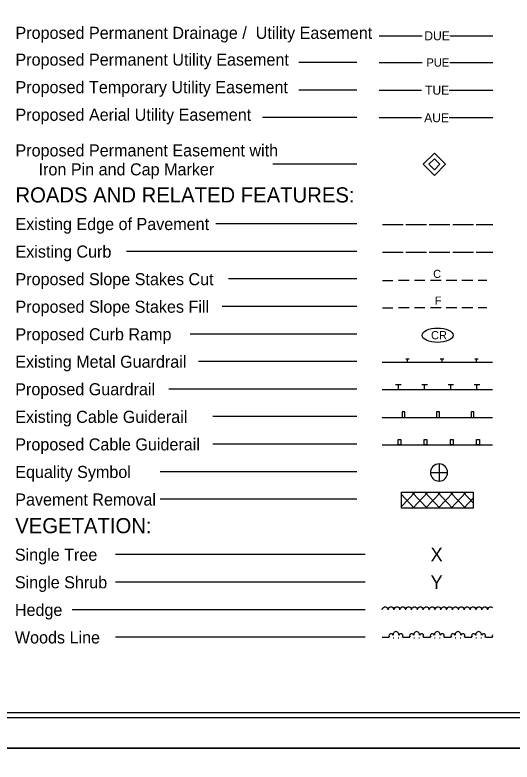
# Model space of a CAD drawing. Extents: x 2241278 to 2254132, y 649924 to 670434.
# Drawn here: x 2247365 to 2249169, y 655349 to 658059 of the extents above; entities that cross this region are included whole.
import ezdxf

# ---------------------------------------------------------------- set-up
doc = ezdxf.new("R2010")
doc.units = 0
for name, color, linetype in [('Prop Easement Permanent Drainage Utility', 7, 'Continuous'), ('Prop ROW Permanent Easement CELL', 7, 'Continuous'), ('Prop WCC CELL', 7, 'Continuous'), ('Sheet Cutting Line CELL', 7, 'Continuous'), ('Sheet Plot Border Inside CELL', 7, 'Continuous'), ('Sheet Plot Border Outside CELL', 7, 'Continuous'), ('Sheet Symbology CELL', 7, 'Continuous')]:
    doc.layers.add(name, color=color, linetype=linetype)

msp = doc.modelspace()

# ---------------------------------------------------------------- linework, layer by layer
at = {"layer": 'Prop Easement Permanent Drainage Utility'}
for p, q in [((2248686.3, 657983.7), (2248842.8, 657983.7)), ((2248942.8, 657983.7), (2249098.8, 657983.7))]:
    msp.add_line(p, q, dxfattribs=at)
at = {"layer": 'Prop ROW Permanent Easement CELL'}
msp.add_line((2248887, 657517.5), (2248887, 657517.5), dxfattribs=at)
for points in [[(2248887, 657557.7), (2248927.2, 657517.5), (2248887, 657477.2), (2248846.7, 657517.5)], [(2248887, 657537.6), (2248907.1, 657517.5), (2248887, 657497.3), (2248866.9, 657517.5)]]:
    msp.add_lwpolyline(points, close=True, dxfattribs=at)
at = {"layer": 'Prop WCC CELL'}
msp.add_ellipse((2248898.6, 656897.4), major_axis=(56.1, 0), ratio=0.462467, dxfattribs=at)
at = {"layer": 'Sheet Cutting Line CELL'}
for p, q in [((2252976.3, 655399.2), (2244558.8, 655399.2)), ((2244558.8, 655399.2), (2252978.8, 655399.2))]:
    msp.add_line(p, q, dxfattribs=at)
at = {"layer": 'Sheet Plot Border Inside CELL'}
msp.add_lwpolyline([(2244623.8, 655511.4), (2252956.3, 655511.4), (2252956.3, 660786.9), (2244623.8, 660786.9)], close=True, dxfattribs=at)
at = {"layer": 'Sheet Plot Border Outside CELL'}
for points in [[(2244558.8, 655399.2), (2252978.8, 655399.2), (2252978.8, 660899.2), (2244558.8, 660899.2)], [(2244558.8, 649924.2), (2252976.3, 649924.2), (2252976.3, 655399.2), (2244558.8, 655399.2)]]:
    msp.add_lwpolyline(points, close=True, dxfattribs=at)
at = {"layer": 'Sheet Symbology CELL'}
for p, q in [((2248606.1, 657886.6), (2248395.4, 657886.6)), ((2248686.3, 657886.6), (2248705.5, 657886.6)), ((2248705.5, 657886.6), (2248843, 657886.6)), ((2248943, 657886.6), (2249080.5, 657886.6)), ((2249080.5, 657886.6), (2249098.8, 657886.6)), ((2248606.1, 657786.6), (2248395.4, 657786.6)), ((2248686.3, 657786.6), (2248703, 657786.6)), ((2248703, 657786.6), (2248840.5, 657786.6)), ((2248940.5, 657786.6), (2249078, 657786.6)), ((2249078, 657786.6), (2249098.8, 657786.6)), ((2248606.1, 657686.6), (2248263.8, 657686.6)), ((2248686.3, 657686.6), (2248703, 657686.6)), ((2248703, 657686.6), (2248840.5, 657686.6)), ((2248940.5, 657686.6), (2249078, 657686.6)), ((2249078, 657686.6), (2249098.8, 657686.6)), ((2248606.1, 657517.5), (2248301.1, 657517.5)), ((2248606.1, 657301.7), (2248094.4, 657301.7)), ((2248698.8, 657298.8), (2248773.8, 657298.8)), ((2248783.8, 657298.8), (2248858.8, 657298.8)), ((2248868.8, 657298.8), (2248943.8, 657298.8)), ((2248953.8, 657298.8), (2249028.8, 657298.8)), ((2249038.8, 657298.8), (2249098.8, 657298.8)), ((2248606.1, 657201.7), (2247770.4, 657201.7)), ((2248698.8, 657198.8), (2248773.8, 657198.8)), ((2248783.8, 657198.8), (2248858.8, 657198.8)), ((2248868.8, 657198.8), (2248943.8, 657198.8)), ((2248953.8, 657198.8), (2249028.8, 657198.8)), ((2249038.8, 657198.8), (2249098.8, 657198.8)), ((2248606.1, 657101.7), (2248140.2, 657101.7)), ((2248698.8, 657096.4), (2248736.8, 657096.4)), ((2248795.3, 657096.4), (2248757.5, 657096.4)), ((2248852.8, 657096.4), (2248814.8, 657096.4)), ((2248911.5, 657096.4), (2248872.5, 657096.4)), ((2248968.8, 657096.4), (2248930, 657096.4)), ((2249026.5, 657096.4), (2248987.3, 657096.4)), ((2249078, 657096.4), (2249046, 657096.4)), ((2248606.1, 657001.7), (2248117.4, 657001.7)), ((2248698.8, 656996.4), (2248736.8, 656996.4)), ((2248795.3, 656996.4), (2248757.5, 656996.4)), ((2248852.8, 656996.4), (2248814.8, 656996.4)), ((2248911.5, 656996.4), (2248872.5, 656996.4)), ((2248968.8, 656996.4), (2248930, 656996.4)), ((2249026.5, 656996.4), (2248987.3, 656996.4)), ((2249078, 656996.4), (2249046, 656996.4)), ((2248606.1, 656901.7), (2248001.5, 656901.7)), ((2248605.3, 656802.3), (2248031.1, 656802.3)), ((2248783.7, 656811.9), (2248796.2, 656811.9)), ((2248789.9, 656799.4), (2248789.9, 656811.9)), ((2248908.7, 656811.9), (2248921.2, 656811.9)), ((2248914.9, 656799.4), (2248914.9, 656811.9)), ((2249033.7, 656811.9), (2249046.2, 656811.9)), ((2249039.9, 656799.4), (2249039.9, 656811.9)), ((2248698, 656799.4), (2249098, 656799.4)), ((2248746.6, 656719.2), (2248766.6, 656719.2)), ((2248756.6, 656699.4), (2248756.6, 656719.2)), ((2248841.6, 656719.2), (2248861.6, 656719.2)), ((2248851.6, 656699.4), (2248851.6, 656719.2)), ((2248936.6, 656719.2), (2248956.6, 656719.2)), ((2248946.6, 656699.4), (2248946.6, 656719.2)), ((2249031.6, 656719.2), (2249051.6, 656719.2)), ((2249041.6, 656699.4), (2249041.6, 656719.2)), ((2248605.3, 656702.3), (2247924.1, 656702.3)), ((2249098, 656699.4), (2248698, 656699.4)), ((2248605.3, 656602.3), (2248083.8, 656602.3)), ((2248698, 656599.4), (2249098, 656599.4)), ((2248605.3, 656502.3), (2248083.8, 656502.3)), ((2248698, 656499.4), (2249098, 656499.4)), ((2248904.1, 656430.6), (2248904.1, 656399.3)), ((2248605.3, 656402.3), (2247892.2, 656402.3)), ((2248872.9, 656399.3), (2248904.1, 656399.3)), ((2248904.1, 656399.3), (2248904.1, 656368.1)), ((2248904.1, 656399.3), (2248935.4, 656399.3)), ((2248767.7, 656328.7), (2249028.2, 656328.7)), ((2248767.7, 656270.2), (2248767.7, 656328.7)), ((2248767.7, 656325.7), (2248770.5, 656328.7)), ((2248767.7, 656276), (2248817, 656328.7)), ((2248814, 656270.2), (2248767.7, 656319.7)), ((2248860.5, 656270.2), (2248805.5, 656328.7)), ((2248808.5, 656270.2), (2248863.5, 656328.7)), ((2248906.7, 656270.2), (2248852, 656328.7)), ((2248854.7, 656270.2), (2248910, 656328.7)), ((2248953.2, 656270.2), (2248898.2, 656328.7)), ((2248901.2, 656270.2), (2248956.2, 656328.7)), ((2248999.7, 656270.2), (2248944.5, 656328.7)), ((2248947.7, 656270.2), (2249002.5, 656328.7)), ((2249028.2, 656289), (2248991, 656328.7)), ((2249028.2, 656328.7), (2249028.2, 656270.2)), ((2248605.3, 656302.3), (2247892.2, 656302.3)), ((2248994, 656270.2), (2249028.2, 656306.7)), ((2249028.2, 656270.2), (2248767.7, 656270.2)), ((2248636, 656101.9), (2247730.4, 656101.9)), ((2248636, 656001.9), (2247730.4, 656001.9)), ((2248698, 655901.9), (2248699.5, 655906.7)), ((2248699.5, 655906.7), (2248702.5, 655909.9)), ((2248702.5, 655909.9), (2248706.5, 655912.2)), ((2248706.5, 655912.2), (2248711.2, 655912.2)), ((2248711.2, 655912.2), (2248715.2, 655909.7)), ((2248715.2, 655909.7), (2248718, 655906.4)), ((2248718, 655906.4), (2248719, 655902.2)), ((2248719.2, 655901.9), (2248720.7, 655906.7)), ((2248720.7, 655906.7), (2248723.7, 655909.9)), ((2248723.7, 655909.9), (2248727.7, 655912.2)), ((2248727.7, 655912.2), (2248732.5, 655912.2)), ((2248732.5, 655912.2), (2248736.5, 655909.7)), ((2248736.5, 655909.7), (2248739.2, 655906.4)), ((2248739.2, 655906.4), (2248740.2, 655902.2)), ((2248740.5, 655901.9), (2248742, 655906.7)), ((2248742, 655906.7), (2248745, 655909.9)), ((2248745, 655909.9), (2248749, 655912.2)), ((2248749, 655912.2), (2248753.7, 655912.2)), ((2248753.7, 655912.2), (2248757.7, 655909.7)), ((2248757.7, 655909.7), (2248760.5, 655906.4)), ((2248760.5, 655906.4), (2248761.5, 655902.2)), ((2248761.7, 655901.9), (2248763.2, 655906.7)), ((2248763.2, 655906.7), (2248766.2, 655909.9)), ((2248766.2, 655909.9), (2248770.2, 655912.2)), ((2248770.2, 655912.2), (2248775, 655912.2)), ((2248775, 655912.2), (2248779, 655909.7)), ((2248779, 655909.7), (2248781.7, 655906.4)), ((2248781.7, 655906.4), (2248782.7, 655902.2)), ((2248783, 655901.9), (2248784.5, 655906.7)), ((2248784.5, 655906.7), (2248787.5, 655909.9)), ((2248787.5, 655909.9), (2248791.5, 655912.2)), ((2248791.5, 655912.2), (2248796.2, 655912.2)), ((2248796.2, 655912.2), (2248800.2, 655909.7)), ((2248800.2, 655909.7), (2248803, 655906.4)), ((2248803, 655906.4), (2248804, 655902.2)), ((2248804.2, 655901.9), (2248805.7, 655906.7)), ((2248805.7, 655906.7), (2248808.7, 655909.9)), ((2248808.7, 655909.9), (2248812.7, 655912.2)), ((2248812.7, 655912.2), (2248817.5, 655912.2)), ((2248817.5, 655912.2), (2248821.5, 655909.7)), ((2248821.5, 655909.7), (2248824.2, 655906.4)), ((2248824.2, 655906.4), (2248825.2, 655902.2)), ((2248825.5, 655901.9), (2248827, 655906.7)), ((2248827, 655906.7), (2248830, 655909.9)), ((2248830, 655909.9), (2248834, 655912.2)), ((2248834, 655912.2), (2248838.7, 655912.2)), ((2248838.7, 655912.2), (2248842.7, 655909.7)), ((2248842.7, 655909.7), (2248845.5, 655906.4)), ((2248845.5, 655906.4), (2248846.5, 655902.2)), ((2248846.7, 655901.9), (2248848.2, 655906.7)), ((2248848.2, 655906.7), (2248851.2, 655909.9)), ((2248851.2, 655909.9), (2248855.2, 655912.2)), ((2248855.2, 655912.2), (2248860, 655912.2)), ((2248860, 655912.2), (2248864, 655909.7)), ((2248864, 655909.7), (2248866.7, 655906.4)), ((2248866.7, 655906.4), (2248867.7, 655902.2)), ((2248868, 655901.9), (2248869.5, 655906.7)), ((2248869.5, 655906.7), (2248872.5, 655909.9)), ((2248872.5, 655909.9), (2248876.5, 655912.2)), ((2248876.5, 655912.2), (2248881.2, 655912.2)), ((2248881.2, 655912.2), (2248885.2, 655909.7)), ((2248885.2, 655909.7), (2248888, 655906.4)), ((2248888, 655906.4), (2248889, 655902.2)), ((2248889.2, 655901.9), (2248890.7, 655906.7)), ((2248890.7, 655906.7), (2248893.7, 655909.9)), ((2248893.7, 655909.9), (2248897.7, 655912.2)), ((2248897.7, 655912.2), (2248902.5, 655912.2)), ((2248902.5, 655912.2), (2248906.5, 655909.7)), ((2248906.5, 655909.7), (2248909.2, 655906.4)), ((2248909.2, 655906.4), (2248910.2, 655902.2)), ((2248910.5, 655901.9), (2248912, 655906.7)), ((2248912, 655906.7), (2248915, 655909.9)), ((2248915, 655909.9), (2248919, 655912.2)), ((2248919, 655912.2), (2248923.7, 655912.2)), ((2248923.7, 655912.2), (2248927.7, 655909.7)), ((2248927.7, 655909.7), (2248930.5, 655906.4)), ((2248930.5, 655906.4), (2248931.5, 655902.2)), ((2248931.7, 655901.9), (2248933.2, 655906.7)), ((2248933.2, 655906.7), (2248936.2, 655909.9)), ((2248936.2, 655909.9), (2248940.2, 655912.2)), ((2248940.2, 655912.2), (2248945, 655912.2)), ((2248945, 655912.2), (2248949, 655909.7)), ((2248949, 655909.7), (2248951.7, 655906.4)), ((2248951.7, 655906.4), (2248952.7, 655902.2)), ((2248953, 655901.9), (2248954.5, 655906.7)), ((2248954.5, 655906.7), (2248957.5, 655909.9)), ((2248957.5, 655909.9), (2248961.5, 655912.2)), ((2248961.5, 655912.2), (2248966.2, 655912.2)), ((2248966.2, 655912.2), (2248970.2, 655909.7)), ((2248970.2, 655909.7), (2248973, 655906.4)), ((2248973, 655906.4), (2248974, 655902.2)), ((2248974.2, 655901.9), (2248975.7, 655906.7)), ((2248975.7, 655906.7), (2248978.7, 655909.9)), ((2248978.7, 655909.9), (2248982.7, 655912.2)), ((2248982.7, 655912.2), (2248987.5, 655912.2)), ((2248987.5, 655912.2), (2248991.5, 655909.7)), ((2248991.5, 655909.7), (2248994.2, 655906.4)), ((2248994.2, 655906.4), (2248995.2, 655902.2)), ((2248995.5, 655901.9), (2248997, 655906.7)), ((2248997, 655906.7), (2249000, 655909.9)), ((2249000, 655909.9), (2249004, 655912.2)), ((2249004, 655912.2), (2249008.7, 655912.2)), ((2249008.7, 655912.2), (2249012.7, 655909.7)), ((2249012.7, 655909.7), (2249015.5, 655906.4)), ((2249015.5, 655906.4), (2249016.5, 655902.2)), ((2249016.7, 655901.9), (2249018.2, 655906.7)), ((2249018.2, 655906.7), (2249021.2, 655909.9)), ((2249021.2, 655909.9), (2249025.2, 655912.2)), ((2249025.2, 655912.2), (2249030, 655912.2)), ((2249030, 655912.2), (2249034, 655909.7)), ((2249034, 655909.7), (2249036.7, 655906.4)), ((2249036.7, 655906.4), (2249037.7, 655902.2)), ((2249038, 655901.9), (2249039.5, 655906.7)), ((2249039.5, 655906.7), (2249042.5, 655909.9)), ((2249042.5, 655909.9), (2249046.5, 655912.2)), ((2249046.5, 655912.2), (2249051.2, 655912.2)), ((2249051.2, 655912.2), (2249055.2, 655909.7)), ((2249055.2, 655909.7), (2249058, 655906.4)), ((2249058, 655906.4), (2249059, 655902.2)), ((2249059.2, 655901.9), (2249060.7, 655906.7)), ((2249060.7, 655906.7), (2249063.7, 655909.9)), ((2249063.7, 655909.9), (2249067.7, 655912.2)), ((2249067.7, 655912.2), (2249072.5, 655912.2)), ((2249072.5, 655912.2), (2249076.5, 655909.7)), ((2249076.5, 655909.7), (2249079.2, 655906.4)), ((2249079.2, 655906.4), (2249080.2, 655902.2)), ((2249080.5, 655901.9), (2249082, 655906.7)), ((2249082, 655906.7), (2249085, 655909.9)), ((2249085, 655909.9), (2249089, 655912.2)), ((2249089, 655912.2), (2249093.7, 655912.2)), ((2249093.7, 655912.2), (2249097.7, 655909.7)), ((2249097.7, 655909.7), (2249098, 655909.4)), ((2248636, 655901.9), (2247572.6, 655901.9)), ((2248636, 655801.9), (2247730.4, 655801.9)), ((2248698, 655801.9), (2248723, 655801.9)), ((2248737.7, 655799.4), (2248740.2, 655799.4)), ((2248755.2, 655799.4), (2248757.7, 655799.4)), ((2248773, 655801.9), (2248798, 655801.9)), ((2248812.7, 655799.4), (2248815.2, 655799.4)), ((2248830.2, 655799.4), (2248832.7, 655799.4)), ((2248848, 655801.9), (2248873, 655801.9)), ((2248887.7, 655799.4), (2248890.2, 655799.4)), ((2248905.2, 655799.4), (2248907.7, 655799.4)), ((2248923, 655801.9), (2248948, 655801.9)), ((2248962.7, 655799.4), (2248965.2, 655799.4)), ((2248980.2, 655799.4), (2248982.7, 655799.4)), ((2248998, 655801.9), (2249023, 655801.9)), ((2249037.7, 655799.4), (2249040.2, 655799.4)), ((2249055.2, 655799.4), (2249057.7, 655799.4)), ((2249073, 655801.9), (2249098, 655801.9))]:
    msp.add_line(p, q, dxfattribs=at)
for points in [[(2252893.8, 660774.2), (2245393.8, 660774.2), (2245393.8, 655529.3), (2252893.8, 655529.3)], [(2248770.4, 656599.4), (2248780.4, 656599.4), (2248780.4, 656619.4), (2248770.4, 656619.4)], [(2248895.4, 656599.4), (2248905.4, 656599.4), (2248905.4, 656619.4), (2248895.4, 656619.4)], [(2249020.4, 656599.4), (2249030.4, 656599.4), (2249030.4, 656619.4), (2249020.4, 656619.4)], [(2248755.3, 656519.4), (2248765.3, 656519.4), (2248765.3, 656499.4), (2248755.3, 656499.4)], [(2248850.3, 656519.4), (2248860.3, 656519.4), (2248860.3, 656499.4), (2248850.3, 656499.4)], [(2248945.3, 656519.4), (2248955.3, 656519.4), (2248955.3, 656499.4), (2248945.3, 656499.4)], [(2249040.3, 656519.4), (2249050.3, 656519.4), (2249050.3, 656499.4), (2249040.3, 656499.4)]]:
    msp.add_lwpolyline(points, close=True, dxfattribs=at)
for centre, radius, start, end in [((2248904.1, 656399.3), 31.2, 89.9944, 179.9989), ((2248904.1, 656399.3), 31.2, 359.9944, 89.9989), ((2248904.1, 656399.3), 31.2, 179.9944, 269.9989), ((2248904.1, 656399.3), 31.2, 269.9944, 359.9989), ((2248730.2, 655807), 7.91, 18.435, 219.2315), ((2248747.7, 655812), 10.3, 345.9638, 194.0362), ((2248765.2, 655807), 7.91, 320.7685, 161.5651), ((2248805.2, 655807), 7.91, 18.435, 219.2315), ((2248822.7, 655812), 10.3, 345.9638, 194.0362), ((2248840.2, 655807), 7.91, 320.7685, 161.5651), ((2248880.2, 655807), 7.91, 18.435, 219.2315), ((2248897.7, 655812), 10.3, 345.9638, 194.0362), ((2248915.2, 655807), 7.91, 320.7685, 161.5651), ((2248955.2, 655807), 7.91, 18.435, 219.2315), ((2248972.7, 655812), 10.3, 345.9638, 194.0362), ((2248990.2, 655807), 7.91, 320.7685, 161.5651), ((2249030.2, 655807), 7.91, 18.435, 219.2315), ((2249047.7, 655812), 10.3, 345.9638, 194.0362), ((2249065.2, 655807), 7.91, 320.7685, 161.5651), ((2249105.2, 655807), 7.91, 156.251, 203.749)]:
    msp.add_arc(centre, radius, start, end, dxfattribs=at)

# ---------------------------------------------------------------- texts
at = {"layer": 'Prop Easement Permanent Drainage Utility'}
msp.add_text('DUE', height=32.75, dxfattribs=at).set_placement((2248850.7, 657967.2))
at = {"layer": 'Prop WCC CELL'}
msp.add_text('CR', height=30, dxfattribs=at).set_placement((2248875, 656882.6))
at = {"layer": 'Sheet Symbology CELL'}
for s, height, p in [('Proposed Permanent Drainage /  Utility Easement', 43.75, (2247367.4, 657972.4)), ('Proposed Permanent Utility Easement', 43.75, (2247367.4, 657875.3)), ('PUE', 30, (2248858.5, 657871.6)), ('Proposed Temporary Utility Easement', 43.75, (2247367.4, 657775.3)), ('TUE', 32.75, (2248853.4, 657770.1)), ('Proposed Aerial Utility Easement', 43.75, (2247367.4, 657675.3)), ('AUE', 32.75, (2248850.1, 657670.1)), ('Proposed Permanent Easement with', 43.75, (2247367.4, 657546)), ('Iron Pin and Cap Marker', 43.75, (2247451.2, 657477.2)), ('ROADS AND RELATED FEATURES:', 55, (2247367.4, 657378.9)), ('Existing Edge of Pavement', 43.75, (2247367.4, 657278.9)), ('Existing Curb', 43.75, (2247367.4, 657178.9)), ('C', 29.6, (2248882.8, 657105.1)), ('Proposed Slope Stakes Cut', 43.75, (2247367.4, 657078.9)), ('Proposed Slope Stakes Fill', 43.75, (2247367.4, 656978.9)), ('F', 29.6, (2248888.8, 657008.2)), ('Proposed Curb Ramp', 43.75, (2247367.4, 656878.9)), ('Existing Metal Guardrail', 43.75, (2247366.6, 656779.5)), ('Proposed Guardrail', 43.75, (2247366.6, 656679.6)), ('Existing Cable Guiderail', 43.75, (2247366.6, 656579.6)), ('Proposed Cable Guiderail', 43.75, (2247366.6, 656479.6)), ('Equality Symbol', 43.75, (2247366.6, 656379.6)), ('Pavement Removal', 43.75, (2247366.6, 656279.6)), ('VEGETATION:', 55, (2247366.6, 656179.2)), ('Single Tree', 43.75, (2247365.2, 656079.3)), ('X', 50, (2248873, 656076.9)), ('Single Shrub', 43.75, (2247365.2, 655979.3)), ('Y', 50, (2248873, 655976.9)), ('Hedge', 43.75, (2247365.2, 655879.3)), ('Woods Line', 43.75, (2247365.2, 655779.3))]:
    msp.add_text(s, height=height, dxfattribs=at).set_placement(p)

doc.saveas('drawing.dxf')
